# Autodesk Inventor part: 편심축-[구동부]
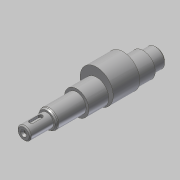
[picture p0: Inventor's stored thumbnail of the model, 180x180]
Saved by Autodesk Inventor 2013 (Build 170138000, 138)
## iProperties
Created: 2019-01
Part Number: 편심축-[구동부]
Material: 강철, 연강
Document SubType Name: Modeling
Designer: mduedu
Density: 7.86 g/cm^3
Mass: 326.79 g
Surface Area: 90.9817 cm^2
Volume: 41.5764 cm^3
Author: mduedu
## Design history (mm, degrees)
sketch "스케치1"
  geometry: L1 (0, 0)-(21, 0); L2 (21, 0)-(21, 6); L3 (21, 6)-(0, 6); L4 (0, 6)-(0, 0); L5 (21, 0)-(48, 0); L6 (48, 0)-(48, 8.5); L7 (48, 8.5)-(21, 8.5); L8 (21, 8.5)-(21, 0); L9 (48, 0)-(108, 0); L10 (108, 0)-(108, 11); L11 (108, 11)-(48, 11); L12 (48, 11)-(48, 0); L13 (108, 0)-(120, 0); L14 (120, 0)-(120, 8.5); L15 (120, 8.5)-(108, 8.5); L16 (108, 8.5)-(108, 0)
  constraints: 32 end point, 8 parallel, 4 horizontal, 4 perpendicular
  dimensions: "d0" = 120 distance between parallel lines of L14 L4; "d2" = 12 distance of L14.end L15.end; "d3" = 60 distance of L10.end L11.end; "d4" = 99 distance between parallel lines of L8 L14; "d5" = 12 diameter of L3 L1; "d6" = 17 diameter of L7 L5; "d7" = 17 diameter of L15 L13; "d8" = 22 diameter of L11 L9
revolve "회전1" sketch "스케치1" stored, may be unused: angle "d9" = 90 deg
node "작업 평면1"
sketch "스케치2"
  geometry: C1 r 15 at (0, 4); C2 r 11 at (0, 0) reference; 1 further point
  constraints: 1 centre point, 1 tangent, 1 vertical alignment
  dimensions: "d11" = 4 distance of point (0, 0) C1.centre
extrude "돌출1" join sketch "스케치2" distance "d12" = 24; taper "d13" = 0 deg
node "작업 평면2"
sketch "스케치3" dims "d16" = 12
  geometry: L1 (-4.5, 2)-(3.5, 2); L2 (3.5, 2)-(3.5, -2); L3 (3.5, -2)-(-4.5, -2); L4 (-4.5, -2)-(-4.5, 2); L5 (-10.5, 8.5)-(-10.5, -8.5) reference; 3 further points
  constraints: 8 end point, 2 midpoint, 2 parallel, 2 vertical alignment, 1 horizontal, 1 horizontal alignment, 1 perpendicular, 4 other
  dimensions: "d14" = 4 distance between parallel lines of L3 L1; "d17" = 4 dimension on L5
extrude "돌출2" cut sketch "스케치3" distance "d18" = 2.5; taper "d19" = 0 deg
chamfer "모따기1" distance "d20" = 1.82; stored, may be unused: second distance "d21" = 2, angle "d22" = 30 deg
fillet "모깎기1" dims "d23" = 2
hole "구멍2" diameter "d39" = 3.242; stored, may be unused: countersink angle "d43" = 60 deg, drill point angle "d45" = 118 deg; dims "d37" = 10, "d38" = 10, "d40" = 8, "d41" = 5.51, "d42" = 2, "d44" = 10
sketch "스케치5"
  geometry: L1 (0, 0)-(2, 0); L2 (2, 0)-(2, 1.621); L3 (0, 2.776)-(0, 0); L4 (0, 2.776)-(2, 1.621); L5 (10, 1.621)-(0, 1.621) reference
  constraints: 8 end point, 1 horizontal, 1 parallel, 1 perpendicular, 1 point on line
  dimensions: "d46" = 2 distance between parallel lines of L2 L3; "d48" = 30 deg angle of L4 L1
revolve "회전2" sketch "스케치5" stored, may be unused: angle "d50" = 90 deg
chamfer "모따기2" distance "d25" = 1; stored, may be unused: second distance "d26" = 2, angle "d27" = 30 deg
node "솔리드1"
